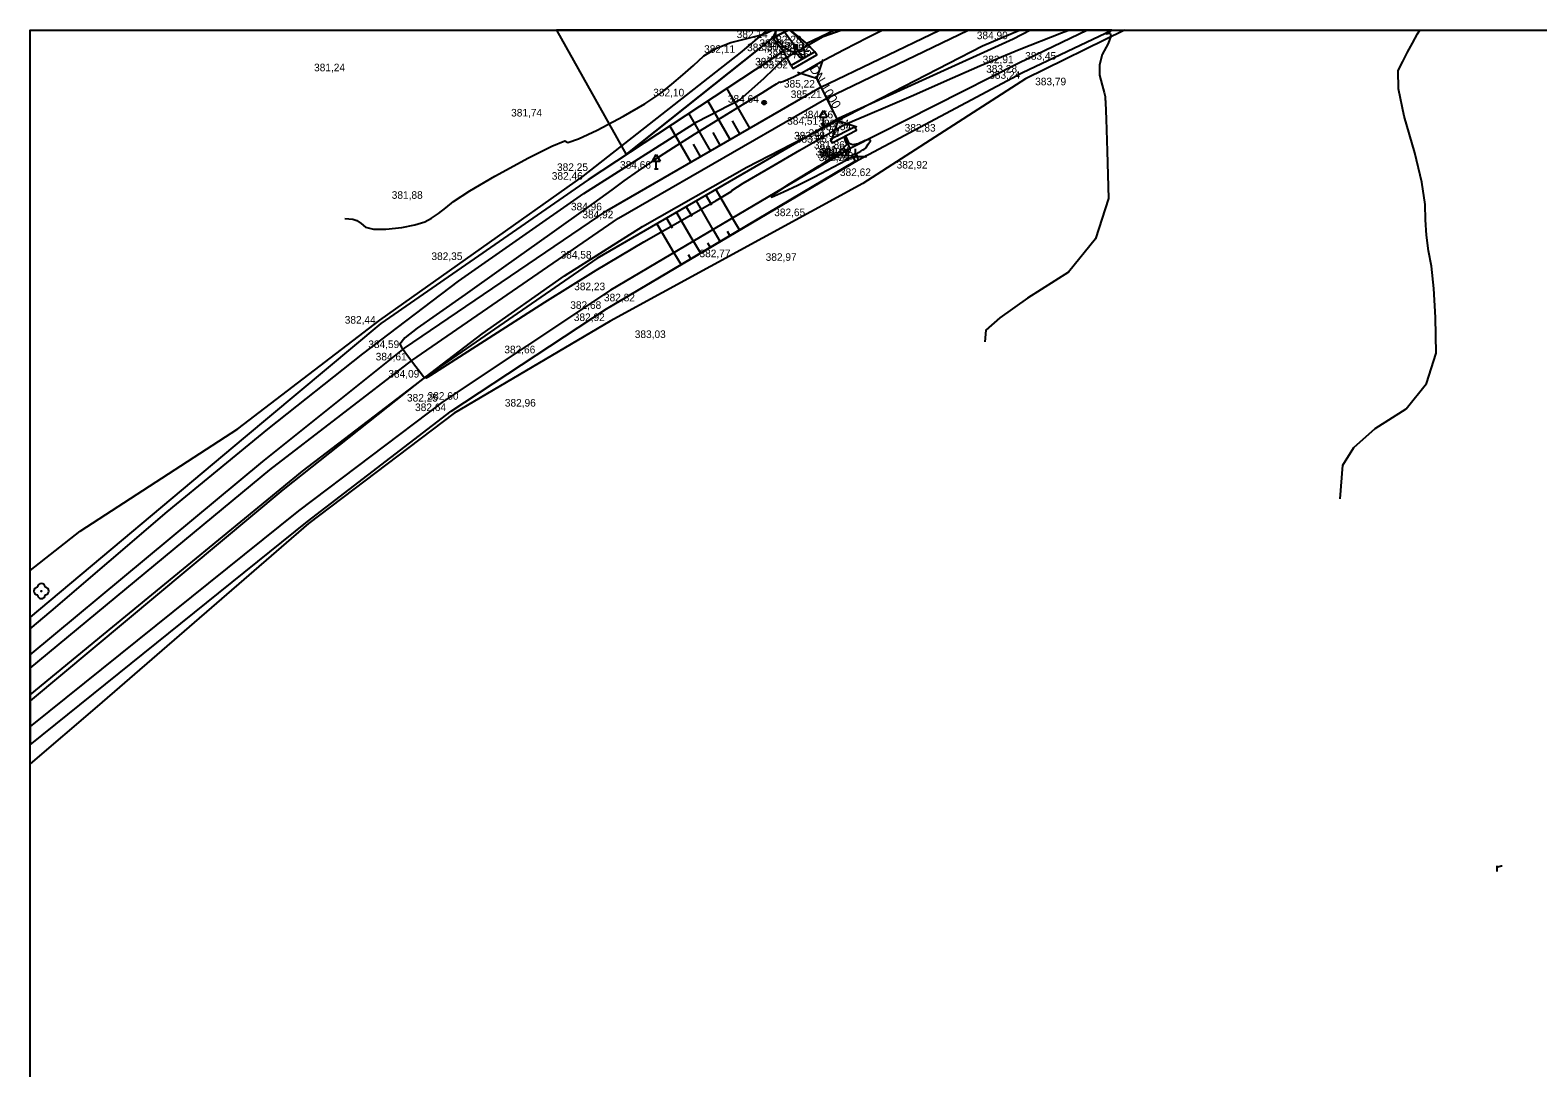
# Model space of a CAD drawing. Extents: x -574342 to -507939, y -1144044 to -1123894.
# Drawn here: x -508866.8 to -508667.6, y -1142984.7 to -1142847.7 of the extents above; entities that cross this region are included whole.
import ezdxf

# ---------------------------------------------------------------- set-up
doc = ezdxf.new("R2010")
doc.units = 0
for name, color, linetype in [('01_DOPRAVA', 7, 'Continuous'), ('01_PARCELY_NAVRH_PC', 7, 'Continuous'), ('01_PARCELY_NAVRH_ZPF', 7, 'Continuous'), ('07_SDĚLOVACÍ', 7, 'Continuous'), ('15', 7, 'Continuous'), ('37', 7, 'Continuous'), ('42', 7, 'Continuous'), ('43', 7, 'Continuous'), ('52', 7, 'Continuous'), ('54', 7, 'Continuous'), ('57', 7, 'Continuous'), ('60', 7, 'Continuous'), ('61', 7, 'Continuous'), ('Level 1', 7, 'Continuous'), ('Level 255', 7, 'Continuous'), ('Level24', 7, 'Continuous'), ('VRST VEDL', 7, 'Continuous')]:
    doc.layers.add(name, color=color, linetype=linetype)

msp = doc.modelspace()

# ---------------------------------------------------------------- linework, layer by layer
at = {"layer": '01_DOPRAVA'}
msp.add_lwpolyline([(-508866.76, -1142931.96), (-508835.1, -1142905.74), (-508816.33, -1142891.31), (-508789.03, -1142872.54), (-508761.51, -1142856.66), (-508742.87, -1142847.7)], dxfattribs=at)
at = {"layer": '01_PARCELY_NAVRH_PC'}
for p, q in [((-508723.89, -1142847.7), (-508766.62, -1142847.7)), ((-508866.76, -1142925.23), (-508866.76, -1142942.06))]:
    msp.add_line(p, q, dxfattribs=at)
for points in [[(-508766.62, -1142847.7), (-508768.65, -1142848.73), (-508788.02, -1142864.13), (-508793.07, -1142867.45), (-508820.42, -1142886.45), (-508838.61, -1142901.61), (-508866.76, -1142925.23)], [(-508866.76, -1142942.06), (-508830.12, -1142912.59), (-508811.13, -1142898), (-508790.63, -1142884.5), (-508757.34, -1142864.81), (-508735.7, -1142853.31), (-508723.89, -1142847.7)]]:
    msp.add_lwpolyline(points, dxfattribs=at)
at = {"layer": '01_PARCELY_NAVRH_ZPF'}
msp.add_line((-508766.62, -1142847.7), (-508797.26, -1142847.7), dxfattribs=at)
msp.add_lwpolyline([(-508797.26, -1142847.7), (-508788.02, -1142864.13), (-508768.65, -1142848.73), (-508766.62, -1142847.7)], dxfattribs=at)
at = {"layer": '07_SDĚLOVACÍ'}
for points in [[(-508866.76, -1142935.49), (-508857.08, -1142927.5), (-508830.8, -1142905.93), (-508820.51, -1142898.12), (-508807.05, -1142887.8), (-508796.16, -1142880.16), (-508785.9, -1142873.62), (-508772.09, -1142865.8), (-508740.98, -1142849.77), (-508736.1, -1142847.7)], [(-508866.76, -1142926.76), (-508863.97, -1142924.43), (-508848.67, -1142911.31), (-508835.38, -1142900.39), (-508822.81, -1142890.44), (-508810.18, -1142880.83), (-508793.63, -1142869.29), (-508778.68, -1142859.79), (-508772.97, -1142856.87), (-508769.85, -1142854.07), (-508767.11, -1142851.46), (-508762.03, -1142848.54), (-508759.65, -1142847.7)]]:
    msp.add_lwpolyline(points, dxfattribs=at)
at = {"layer": '37'}
msp.add_lwpolyline([(-508866.76, -1142931.96), (-508835.1, -1142905.74), (-508816.33, -1142891.31), (-508789.03, -1142872.54), (-508761.51, -1142856.66), (-508742.87, -1142847.7)], dxfattribs=at)
msp.add_lwpolyline([(-508866.76, -1142931.96), (-508835.1, -1142905.74), (-508816.33, -1142891.31), (-508789.03, -1142872.54), (-508761.51, -1142856.66), (-508742.87, -1142847.7)], dxfattribs=at)
at = {"layer": '42'}
for points in [[(-508722.19, -1142847.7), (-508735.29, -1142854.12), (-508756.76, -1142867.95), (-508790.16, -1142886.11), (-508810.74, -1142898.28), (-508829.98, -1142912.85), (-508857.91, -1142937.01), (-508866.76, -1142944.57)], [(-508866.76, -1142919.04), (-508860.14, -1142913.86), (-508839.31, -1142900.36), (-508820.57, -1142886), (-508793.71, -1142866.99), (-508772.95, -1142850.69), (-508769.37, -1142847.7)], [(-508722.19, -1142847.7), (-508735.29, -1142854.12), (-508756.76, -1142867.95), (-508790.16, -1142886.11), (-508810.74, -1142898.28), (-508829.98, -1142912.85), (-508857.91, -1142937.01), (-508866.76, -1142944.57)], [(-508866.76, -1142919.04), (-508860.14, -1142913.86), (-508839.31, -1142900.36), (-508820.57, -1142886), (-508793.71, -1142866.99), (-508772.95, -1142850.69), (-508769.37, -1142847.7)]]:
    msp.add_lwpolyline(points, dxfattribs=at)
at = {"layer": '43'}
for points in [[(-508672.98, -1142958.78), (-508672.98, -1142958.05)], [(-508672.98, -1142958.28), (-508672.87, -1142958.19), (-508672.77, -1142958.13), (-508672.61, -1142958.08), (-508672.46, -1142958.06), (-508672.31, -1142958.05)]]:
    msp.add_lwpolyline(points, dxfattribs=at)
at = {"layer": '52'}
for p, q in [((-508765.89, -1142849.92), (-508765.39, -1142849.92)), ((-508762.48, -1142859.18), (-508761.98, -1142858.33)), ((-508761.98, -1142858.33), (-508761.48, -1142859.18)), ((-508762.48, -1142859.18), (-508761.48, -1142859.18)), ((-508762.23, -1142860.18), (-508761.73, -1142860.18)), ((-508761.98, -1142860.18), (-508761.98, -1142859.18)), ((-508784.56, -1142864.99), (-508784.06, -1142864.14)), ((-508784.56, -1142864.99), (-508783.56, -1142864.99)), ((-508784.06, -1142864.14), (-508783.56, -1142864.99)), ((-508784.06, -1142865.99), (-508784.06, -1142864.99)), ((-508757.78, -1142863.38), (-508757.78, -1142864.38)), ((-508757.78, -1142864.38), (-508756.28, -1142864.38)), ((-508756.28, -1142864.38), (-508756.53, -1142864.28)), ((-508756.28, -1142864.38), (-508756.53, -1142864.48)), ((-508784.31, -1142865.99), (-508783.81, -1142865.99))]:
    msp.add_line(p, q, dxfattribs=at)
msp.add_lwpolyline([(-508765.89, -1142850.17), (-508765.39, -1142850.17), (-508765.39, -1142849.67), (-508765.89, -1142849.67)], close=True, dxfattribs=at)
for radius in [0.25, 0.158, 0.05]:
    msp.add_circle((-508769.81, -1142857.27), radius, dxfattribs=at)
at = {"layer": '54'}
msp.add_circle((-508865.28, -1142921.77), 0.05, dxfattribs=at)
for centre, start, end in [((-508865.28, -1142921.27), 0, 180), ((-508865.78, -1142921.77), 90, 270), ((-508865.28, -1142922.27), 180, 0), ((-508864.78, -1142921.77), 270, 90)]:
    msp.add_arc(centre, 0.5, start, end, dxfattribs=at)
at = {"layer": '57'}
for points in [[(-508766.22, -1142852.36), (-508765.96, -1142852.75), (-508762.87, -1142850.96), (-508763.12, -1142850.58)], [(-508766.22, -1142852.36), (-508765.96, -1142852.75), (-508762.87, -1142850.96), (-508763.12, -1142850.58)], [(-508761.07, -1142862.13), (-508760.84, -1142862.56), (-508757.62, -1142860.91), (-508757.86, -1142860.52)], [(-508761.07, -1142862.13), (-508760.84, -1142862.56), (-508757.62, -1142860.91), (-508757.86, -1142860.52)]]:
    msp.add_lwpolyline(points, close=True, dxfattribs=at)
msp.add_lwpolyline([(-508758, -1142864.62), (-508757.8, -1142864.99), (-508757.34, -1142864.81), (-508757.55, -1142864.31), (-508758, -1142864.62), (-508758.24, -1142864.25), (-508757.69, -1142863.96), (-508757.55, -1142864.31)], dxfattribs=at)
msp.add_lwpolyline([(-508758, -1142864.62), (-508757.8, -1142864.99), (-508757.34, -1142864.81), (-508757.55, -1142864.31), (-508758, -1142864.62), (-508758.24, -1142864.25), (-508757.69, -1142863.96), (-508757.55, -1142864.31)], dxfattribs=at)
at = {"layer": '60'}
for p, q in [((-508766.22, -1142852.36), (-508767.27, -1142850.47)), ((-508766.22, -1142852.36), (-508767.27, -1142850.47)), ((-508763.12, -1142850.58), (-508764.17, -1142849.44)), ((-508763.12, -1142850.58), (-508764.17, -1142849.44)), ((-508758.45, -1142863.34), (-508759.15, -1142861.79)), ((-508758.45, -1142863.34), (-508759.15, -1142861.79))]:
    msp.add_line(p, q, dxfattribs=at)
for points in [[(-508734.65, -1142847.7), (-508736.93, -1142848.89), (-508760, -1142859.35), (-508791.91, -1142877.86), (-508814.66, -1142893.58), (-508833.4, -1142908.42), (-508866.76, -1142936.25)], [(-508727.09, -1142847.7), (-508736.16, -1142852.06), (-508758.45, -1142863.34), (-508790.11, -1142882.04), (-508812.2, -1142896.74), (-508831.32, -1142911.18), (-508866.76, -1142939.66)], [(-508866.76, -1142930.17), (-508836.02, -1142904.68), (-508817.31, -1142889.68), (-508790.54, -1142871.5), (-508762.41, -1142855.28), (-508746.66, -1142847.7)], [(-508734.65, -1142847.7), (-508736.93, -1142848.89), (-508760, -1142859.35), (-508791.91, -1142877.86), (-508814.66, -1142893.58), (-508833.4, -1142908.42), (-508866.76, -1142936.25)], [(-508727.09, -1142847.7), (-508736.16, -1142852.06), (-508758.45, -1142863.34), (-508790.11, -1142882.04), (-508812.2, -1142896.74), (-508831.32, -1142911.18), (-508866.76, -1142939.66)], [(-508866.76, -1142930.17), (-508836.02, -1142904.68), (-508817.31, -1142889.68), (-508790.54, -1142871.5), (-508762.41, -1142855.28), (-508746.66, -1142847.7)], [(-508768.24, -1142847.7), (-508768.65, -1142848.73), (-508767.27, -1142850.47)], [(-508768.24, -1142847.7), (-508768.65, -1142848.73), (-508767.27, -1142850.47)], [(-508767.3, -1142847.7), (-508765.64, -1142849.92), (-508765.38, -1142850.34), (-508764.65, -1142851.41)], [(-508767.3, -1142847.7), (-508765.64, -1142849.92), (-508765.38, -1142850.34), (-508764.65, -1142851.41)], [(-508764.17, -1142849.44), (-508766.35, -1142847.7)], [(-508764.17, -1142849.44), (-508766.35, -1142847.7)], [(-508760.46, -1142847.7), (-508764.17, -1142849.44)], [(-508760.46, -1142847.7), (-508764.17, -1142849.44)], [(-508757.34, -1142864.81), (-508735.7, -1142853.31), (-508723.89, -1142847.7)], [(-508757.34, -1142864.81), (-508735.7, -1142853.31), (-508723.89, -1142847.7)], [(-508767.27, -1142850.47), (-508793.07, -1142867.45), (-508820.42, -1142886.45), (-508838.61, -1142901.61), (-508866.76, -1142925.23)], [(-508767.27, -1142850.47), (-508793.07, -1142867.45), (-508820.42, -1142886.45), (-508838.61, -1142901.61), (-508866.76, -1142925.23)], [(-508866.76, -1142942.06), (-508830.12, -1142912.59), (-508811.13, -1142898), (-508790.63, -1142884.5), (-508757.8, -1142864.99)], [(-508866.76, -1142942.06), (-508830.12, -1142912.59), (-508811.13, -1142898), (-508790.63, -1142884.5), (-508757.8, -1142864.99)]]:
    msp.add_lwpolyline(points, dxfattribs=at)
at = {"layer": '61'}
for p, q in [((-508774.3, -1142862.13), (-508777.24, -1142857.03)), ((-508774.3, -1142862.13), (-508777.24, -1142857.03)), ((-508771.7, -1142860.64), (-508774.73, -1142855.38)), ((-508771.7, -1142860.64), (-508774.73, -1142855.38)), ((-508776.9, -1142863.63), (-508779.75, -1142858.68)), ((-508776.9, -1142863.63), (-508779.75, -1142858.68)), ((-508779.5, -1142865.13), (-508782.26, -1142860.34)), ((-508779.5, -1142865.13), (-508782.26, -1142860.34)), ((-508773, -1142861.39), (-508773.99, -1142859.66)), ((-508773, -1142861.39), (-508773.99, -1142859.66)), ((-508778.2, -1142864.38), (-508779.13, -1142862.76)), ((-508778.2, -1142864.38), (-508779.13, -1142862.76)), ((-508775.6, -1142862.88), (-508776.56, -1142861.21)), ((-508775.6, -1142862.88), (-508776.56, -1142861.21)), ((-508776.2, -1142868.75), (-508774.01, -1142872.53)), ((-508776.2, -1142868.75), (-508774.01, -1142872.53)), ((-508780.1, -1142871.01), (-508779.36, -1142872.28)), ((-508780.1, -1142871.01), (-508779.36, -1142872.28)), ((-508778.8, -1142870.25), (-508776.59, -1142874.06)), ((-508778.8, -1142870.25), (-508776.59, -1142874.06)), ((-508777.5, -1142869.5), (-508776.77, -1142870.76)), ((-508777.5, -1142869.5), (-508776.77, -1142870.76)), ((-508782.69, -1142872.51), (-508781.95, -1142873.79)), ((-508782.69, -1142872.51), (-508781.95, -1142873.79)), ((-508781.39, -1142871.76), (-508779.18, -1142875.58)), ((-508781.39, -1142871.76), (-508779.18, -1142875.58)), ((-508773.05, -1142874.05), (-508773.97, -1142872.51)), ((-508773.05, -1142874.05), (-508773.97, -1142872.51)), ((-508783.99, -1142873.26), (-508781.76, -1142877.11)), ((-508783.99, -1142873.26), (-508781.76, -1142877.11)), ((-508775.63, -1142875.59), (-508776.55, -1142874.03)), ((-508775.63, -1142875.59), (-508776.55, -1142874.03)), ((-508774.34, -1142874.82), (-508774.65, -1142874.3)), ((-508774.34, -1142874.82), (-508774.65, -1142874.3)), ((-508778.21, -1142877.12), (-508779.14, -1142875.56)), ((-508778.21, -1142877.12), (-508779.14, -1142875.56)), ((-508776.92, -1142876.35), (-508777.23, -1142875.83)), ((-508776.92, -1142876.35), (-508777.23, -1142875.83)), ((-508780.79, -1142878.65), (-508781.72, -1142877.08)), ((-508780.79, -1142878.65), (-508781.72, -1142877.08)), ((-508779.5, -1142877.89), (-508779.81, -1142877.37)), ((-508779.5, -1142877.89), (-508779.81, -1142877.37))]:
    msp.add_line(p, q, dxfattribs=at)
at = {"layer": 'Level 1'}
msp.add_lwpolyline([(-508026.76, -1142847.7), (-508026.76, -1144035.7), (-508866.76, -1144035.7), (-508866.76, -1142847.7)], close=True, dxfattribs=at)
at = {"layer": 'Level24'}
for points in [[(-508762.06, -1142851.58), (-508762.89, -1142854.1), (-508765.41, -1142853.28)], [(-508762.89, -1142854.1), (-508760.08, -1142859.68)], [(-508757.56, -1142860.51), (-508760.08, -1142859.68), (-508760.9, -1142862.2)]]:
    msp.add_lwpolyline(points, dxfattribs=at)
at = {"layer": 'VRST VEDL'}
for points in [[(-508825.2, -1142872.58), (-508824.13, -1142872.66), (-508823.59, -1142872.85), (-508823.03, -1142873.21), (-508822.47, -1142873.72), (-508821.39, -1142873.98), (-508819.78, -1142873.99), (-508817.66, -1142873.75), (-508815.95, -1142873.42), (-508814.65, -1142873.01), (-508813.76, -1142872.52), (-508812.83, -1142871.91), (-508811.86, -1142871.17), (-508810.85, -1142870.31), (-508808.69, -1142868.92), (-508805.39, -1142867), (-508800.95, -1142864.56), (-508797.85, -1142863), (-508796.12, -1142862.33), (-508795.73, -1142862.55), (-508794.32, -1142862.07), (-508791.86, -1142860.9), (-508788.37, -1142859.04), (-508785.57, -1142857.41), (-508783.44, -1142856), (-508782, -1142854.82), (-508780.57, -1142853.61), (-508779.16, -1142852.36), (-508777.76, -1142851.09), (-508776.11, -1142850.07), (-508774.22, -1142849.32), (-508772.09, -1142848.82), (-508770.5, -1142848.4), (-508769.45, -1142848.05), (-508768.94, -1142847.79), (-508768.68, -1142847.7)], [(-508754.12, -1142847.7), (-508756.14, -1142848.72), (-508759.24, -1142850.3), (-508760.99, -1142851.21), (-508762.41, -1142851.97), (-508763.48, -1142852.57), (-508764.22, -1142853.02), (-508765.01, -1142853.45), (-508765.84, -1142853.87), (-508766.73, -1142854.28), (-508767.34, -1142854.53), (-508767.67, -1142854.63), (-508767.73, -1142854.57), (-508767.92, -1142854.63), (-508768.23, -1142854.81), (-508768.68, -1142855.11), (-508770.11, -1142856), (-508772.53, -1142857.49), (-508775.95, -1142859.57), (-508779.05, -1142861.49), (-508781.83, -1142863.24), (-508784.3, -1142864.84), (-508786.47, -1142866.29), (-508788.35, -1142867.6), (-508789.93, -1142868.77), (-508793.1, -1142871.06), (-508797.87, -1142874.47), (-508804.23, -1142879), (-508809.32, -1142882.6), (-508813.12, -1142885.28), (-508815.64, -1142887.04), (-508817.25, -1142888.34), (-508817.94, -1142889.18), (-508817.71, -1142889.56), (-508817.28, -1142890.18), (-508816.64, -1142891.03), (-508815.81, -1142892.11), (-508815.2, -1142892.89), (-508814.83, -1142893.37), (-508814.68, -1142893.55), (-508814.47, -1142893.59), (-508814.18, -1142893.5), (-508813.83, -1142893.26), (-508811.15, -1142891.53), (-508806.14, -1142888.31), (-508798.8, -1142883.6), (-508792, -1142879.38), (-508785.72, -1142875.65), (-508779.98, -1142872.4), (-508776.13, -1142870.19), (-508774.17, -1142869.02), (-508774.1, -1142868.88), (-508772.56, -1142867.92), (-508769.55, -1142866.14), (-508765.08, -1142863.54), (-508761.9, -1142861.7), (-508760.02, -1142860.62), (-508759.42, -1142860.31), (-508758.13, -1142859.72), (-508756.14, -1142858.86), (-508753.46, -1142857.72), (-508750.1, -1142856.27), (-508746.05, -1142854.5), (-508741.31, -1142852.41), (-508736.14, -1142850.27), (-508730.53, -1142848.06), (-508729.56, -1142847.7)], [(-508768.38, -1142847.7), (-508768.36, -1142847.79), (-508768.33, -1142847.99), (-508768.29, -1142848.25), (-508768.26, -1142848.57), (-508768.08, -1142848.95), (-508767.76, -1142849.37), (-508767.3, -1142849.85), (-508766.95, -1142850.18), (-508766.7, -1142850.35), (-508766.56, -1142850.38), (-508766.37, -1142850.44), (-508766.13, -1142850.52), (-508765.84, -1142850.63), (-508765.57, -1142850.79), (-508765.32, -1142851.01), (-508765.09, -1142851.27), (-508764.89, -1142851.42), (-508764.72, -1142851.46), (-508764.59, -1142851.38), (-508764.49, -1142851.24), (-508764.44, -1142851.04), (-508764.44, -1142850.78), (-508764.46, -1142850.53), (-508764.52, -1142850.29), (-508764.61, -1142850.06), (-508764.65, -1142849.87), (-508764.64, -1142849.74), (-508764.59, -1142849.65), (-508764.76, -1142849.38), (-508765.15, -1142848.95), (-508765.76, -1142848.33), (-508766.19, -1142847.91), (-508766.41, -1142847.7)], [(-508724.18, -1142847.7), (-508724.35, -1142847.83), (-508724.62, -1142848.19), (-508724.12, -1142848.09), (-508724.03, -1142848.51), (-508724.38, -1142849.44), (-508725.14, -1142850.9), (-508725.53, -1142852.3), (-508725.53, -1142853.66), (-508725.16, -1142854.97), (-508724.91, -1142855.91), (-508724.78, -1142856.48), (-508724.78, -1142856.67), (-508724.76, -1142856.86), (-508724.74, -1142857.06), (-508724.7, -1142857.25), (-508724.62, -1142859.46), (-508724.5, -1142863.69), (-508724.33, -1142869.93), (-508726.03, -1142875.25), (-508729.6, -1142879.64), (-508735.04, -1142883.11), (-508738.69, -1142885.68), (-508740.54, -1142887.33), (-508740.66, -1142888.84)], [(-508693.73, -1142909.58), (-508693.39, -1142905.15), (-508691.91, -1142902.8), (-508689.11, -1142900.31), (-508685.01, -1142897.69), (-508682.31, -1142894.38), (-508681.03, -1142890.36), (-508681.15, -1142885.65), (-508681.37, -1142881.82), (-508681.67, -1142878.88), (-508682.06, -1142876.82), (-508682.33, -1142874.78), (-508682.47, -1142872.75), (-508682.48, -1142870.74), (-508682.95, -1142867.79), (-508683.88, -1142863.89), (-508685.27, -1142859.06), (-508686, -1142855.44), (-508686.05, -1142853.03), (-508685.44, -1142851.83), (-508684.82, -1142850.62), (-508684.17, -1142849.41), (-508683.51, -1142848.2), (-508683.18, -1142847.7)]]:
    msp.add_lwpolyline(points, dxfattribs=at)
msp.add_lwpolyline([(-508759.01, -1142861.71), (-508759.21, -1142861.81), (-508759.2, -1142862), (-508759.09, -1142862.33), (-508758.87, -1142862.8), (-508760.03, -1142863.91), (-508762.57, -1142865.66), (-508766.5, -1142868.04), (-508768.59, -1142869.4), (-508768.85, -1142869.74), (-508767.26, -1142869.07), (-508765.37, -1142868.18), (-508763.16, -1142867.08), (-508760.65, -1142865.75), (-508758.98, -1142864.86), (-508758.15, -1142864.4), (-508758.17, -1142864.37), (-508758.14, -1142864.36), (-508758.08, -1142864.39), (-508757.97, -1142864.43), (-508757.88, -1142864.45), (-508757.81, -1142864.44), (-508757.75, -1142864.39), (-508757.7, -1142864.33), (-508757.68, -1142864.25), (-508757.67, -1142864.14), (-508757.56, -1142864.01), (-508757.34, -1142863.85), (-508757.02, -1142863.67), (-508756.77, -1142863.52), (-508756.59, -1142863.4), (-508756.47, -1142863.31), (-508756.3, -1142863.1), (-508756.06, -1142862.76), (-508755.77, -1142862.3), (-508755.9, -1142862.13), (-508756.45, -1142862.27), (-508757.41, -1142862.7), (-508758.13, -1142862.83), (-508758.59, -1142862.66)], close=True, dxfattribs=at)

# ---------------------------------------------------------------- texts
at = {"layer": '15'}
msp.add_text('DN 1000', height=1.2, rotation=301.1466, dxfattribs=at).set_placement((-508763.87, -1142852.79))
msp.add_text('DN 1000', height=1.2, rotation=301.1466, dxfattribs=at).set_placement((-508763.87, -1142852.79))
at = {"layer": 'Level 255'}
for s, p in [('382,14', (-508773.44, -1142848.73)), ('381,15', (-508770.43, -1142849.92)), ('382,28', (-508768.96, -1142849.44)), ('384,90', (-508741.72, -1142848.89)), ('382,11', (-508777.74, -1142850.69)), ('382,30', (-508772.06, -1142850.47)), ('381,63', (-508770.17, -1142850.34)), ('381,77', (-508769.44, -1142851.41)), ('383,52', (-508767.91, -1142850.58)), ('383,55', (-508767.66, -1142850.96)), ('382,91', (-508740.95, -1142852.06)), ('383,45', (-508735.33, -1142851.6)), ('381,24', (-508829.26, -1142853.13)), ('383,50', (-508771.01, -1142852.36)), ('383,52', (-508770.75, -1142852.75)), ('383,28', (-508740.49, -1142853.31)), ('383,24', (-508740.08, -1142854.12)), ('385,22', (-508767.2, -1142855.28)), ('383,79', (-508734.01, -1142854.98)), ('382,10', (-508784.46, -1142856.44)), ('384,64', (-508774.6, -1142857.27)), ('385,21', (-508766.3, -1142856.66)), ('381,74', (-508803.23, -1142859.1)), ('384,56', (-508764.79, -1142859.35)), ('384,51', (-508766.77, -1142860.18)), ('383,58', (-508765.86, -1142862.13)), ('381,84', (-508763.94, -1142861.79)), ('383,54', (-508762.65, -1142860.52)), ('383,54', (-508762.41, -1142860.91)), ('382,83', (-508751.25, -1142861.09)), ('383,56', (-508765.63, -1142862.56)), ('381,86', (-508763.24, -1142863.34)), ('381,94', (-508762.48, -1142863.96)), ('384,66', (-508788.85, -1142865.99)), ('381,93', (-508763.03, -1142864.25)), ('382,22', (-508762.79, -1142864.62)), ('382,22', (-508762.59, -1142864.99)), ('381,85', (-508762.57, -1142864.38)), ('382,22', (-508762.34, -1142864.31)), ('382,28', (-508762.13, -1142864.81)), ('382,92', (-508752.31, -1142865.97)), ('382,46', (-508797.86, -1142867.45)), ('382,25', (-508797.17, -1142866.29)), ('382,62', (-508759.8, -1142866.96)), ('381,88', (-508819, -1142869.97)), ('384,96', (-508795.33, -1142871.5)), ('384,92', (-508793.82, -1142872.54)), ('382,65', (-508768.48, -1142872.26)), ('382,35', (-508813.76, -1142878.05)), ('384,58', (-508796.7, -1142877.86)), ('382,77', (-508778.35, -1142877.68)), ('382,97', (-508769.61, -1142878.16)), ('382,23', (-508794.9, -1142882.04)), ('382,82', (-508790.97, -1142883.51)), ('382,68', (-508795.42, -1142884.5)), ('382,44', (-508825.21, -1142886.45)), ('382,92', (-508794.95, -1142886.11)), ('384,59', (-508822.1, -1142889.68)), ('383,03', (-508786.9, -1142888.35)), ('384,61', (-508821.12, -1142891.31)), ('382,66', (-508804.13, -1142890.37)), ('384,09', (-508819.45, -1142893.58)), ('382,25', (-508816.99, -1142896.74)), ('382,64', (-508815.92, -1142898)), ('382,60', (-508814.27, -1142896.5)), ('382,96', (-508804.06, -1142897.41))]:
    msp.add_text(s, height=1, dxfattribs=at).set_placement(p)

doc.saveas('drawing.dxf')
